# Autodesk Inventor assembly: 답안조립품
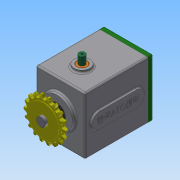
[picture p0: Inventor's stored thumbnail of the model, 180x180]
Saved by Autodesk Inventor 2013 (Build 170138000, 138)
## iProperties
Created: 2018-12
Part Number: 답안조립품
Document SubType Name: Assembly
Designer: Administrator
Author: Administrator
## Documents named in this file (16)
- C:\Users\Administrator\Desktop\381207V1034\답안조립품.iam
- C:\Users\Administrator\Desktop\381207V1034\본체.ipt
- C:\Users\Administrator\Desktop\381207V1034\커버.ipt
- C:\Users\Administrator\Desktop\381207V1034\메인 기어 축.ipt
- C:\Users\Administrator\Desktop\381207V1034\서브 기어 축.ipt
- C:\Users\Administrator\Desktop\381207V1034\베어링 608.ipt
- C:\Users\Administrator\Desktop\381207V1034\베어링 6003.ipt
- C:\Users\Administrator\Desktop\381207V1034\오일 실 8 22 7.ipt
- C:\Users\Administrator\Desktop\381207V1034\오일 실 17 32 8.ipt
- C:\Users\Administrator\Desktop\381207V1034\키 5 x 5 x 18.ipt
- C:\Users\Administrator\Desktop\381207V1034\스프로킷.ipt
- C:\Users\Administrator\Desktop\381207V1034\멈춤나사 M3x8.ipt
- C:\Users\Administrator\Desktop\381207V1034\부시.ipt
- C:\Users\Administrator\Desktop\381207V1034\슬라이더.ipt
- C:\Users\Administrator\Desktop\381207V1034\가변스프링.ipt
- C:\Users\Administrator\Desktop\381207V1034\볼트 M4 x 10.ipt
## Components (1 placed, 1 different names)
1. 가변스프링:1
